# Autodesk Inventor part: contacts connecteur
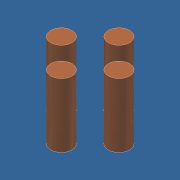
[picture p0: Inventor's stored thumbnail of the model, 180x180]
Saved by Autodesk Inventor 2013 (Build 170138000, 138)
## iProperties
Created: 2011-10
Part Number: contacts connecteur
Material: Cuivre
Document SubType Name: Modeling
Designer: Laur
Mass: 0.0842575 g
Surface Area: 0.439823 cm^2
Volume: 0.00942478 cm^3
Density: 8.94 g/cm^3
Author: Laur
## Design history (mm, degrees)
sketch "Esquisse1"
  geometry: L1 (4.806, 0.4)-(3.456, 0.4); L2 (4.806, 0.4)-(6.156, 0.4); L3 (4.806, 0.4)-(4.806, 1.75); L4 (4.806, 0.4)-(4.806, -0.95); C1 r 0.5 at (4.806, 1.75); C2 r 0.5 at (3.456, 0.4); C3 r 0.5 at (4.806, -0.95); C4 r 0.5 at (6.156, 0.4); C5 r 3.15 at (4.806, 0.4) reference; A1 r 1.35 centre (4.806, 0.4) between (4.806, 1.75) and (3.456, 0.4); 1 further point
  constraints: 8 end point, 5 centre point, 5 coincident, 4 point on circle, 2 collinear, 2 point on line, 1 perpendicular, 1 vertical
  dimensions: "d0" = 1 diameter of C1; "d1" = 1 diameter of C2 (= d0); "d2" = 1 diameter of C3 (= d0); "d3" = 1 diameter of C4 (= d0); "d4" = 2.7 diameter of A1
extrude "Extrusion1" new body sketch "Esquisse1" distance "d5" = 3; taper "d6" = 0 deg
node "Solide1"
node "Corps solides"
node "Corps surfaciques"
node "Référence2"
